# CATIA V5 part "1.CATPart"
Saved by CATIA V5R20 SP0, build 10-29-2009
Part number: 1
Material "Steel": density 7860 kg/m3, Young's modulus 2e+11 Pa, Poisson ratio 0.266, thermal expansion 1.17e-05 1/K
Bounding box of the stored display mesh (mm): x -152.5 to 152.5, y -205 to 205, z -23 to 0
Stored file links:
  E:\Ehsan\Amoozesh\CATIA\CATIA Course\Advanced\Videos\Session-15\1.CATPart
  D:\CATIA V5R20\B20\intel_a\startup\materials\Catalog.CATMaterial
  D:\CATIA V5R20\B20\intel_a\resources\graphic\figures\CATIA_EnvironmentMap_Satin_512x512.jpg
  D:\CATIA V5R20\B20\intel_a\resources\graphic\figures\CATIA_EnvironmentMap_Soft_512x512.jpg
  D:\CATIA V5R20\B20\intel_a\resources\graphic\figures\CATIA_EnvironmentMap_YellowSatin_512x512.jpg
  D:\CATIA V5R20\B20\intel_a\resources\graphic\figures\CATIA_EnvironmentMap_Black_512x512.jpg
  D:\CATIA V5R20\B20\intel_a\resources\graphic\figures\CATIA_EnvironmentMap_Grey_512x512.jpg
  D:\CATIA V5R20\B20\intel_a\resources\graphic\figures\CATIA_EnvironmentMap_DSRed_512x512.jpg
  D:\CATIA V5R20\B20\intel_a\resources\graphic\figures\CATIA_EnvironmentMap_DSBrown_512x512.jpg
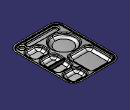
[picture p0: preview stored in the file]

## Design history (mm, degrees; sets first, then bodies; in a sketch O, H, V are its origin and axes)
SheetMetalParameters1: Thickness 0.5, BendRadius 4, KFactor 0.5 {= log(min(100,max(20*SheetMetalParameters1.BendRadius,SheetMetalParameters1.Thickness)/SheetMetalParameters1.Thickness))/log(100)/2}, ReliefRadialLength 1, ReliefAxialLength 2, MinimumBendRadius 0
Body1 (main body), material "Steel"
  Sketch1 on xy-plane, origin (0, 0, 0), H (0, -1, 0), V (1, 0, 0)
    line L1 (205, 102.5) -> (205, -102.5)
    line L2 (155, -152.5) -> (-155, -152.5)
    line L3 (-205, -102.5) -> (-205, 102.5)
    line L4 (-155, 152.5) -> (155, 152.5)
    arc A1 centre (155, 102.5) radius 50 from (205, 102.5) to (155, 152.5) ccw
    arc A2 centre (155, -102.5) radius 50 from (205, -102.5) to (155, -152.5) cw
    arc A3 centre (-155, -102.5) radius 50 from (-155, -152.5) to (-205, -102.5) cw
    arc A4 centre (-155, 102.5) radius 50 from (-205, 102.5) to (-155, 152.5) cw
    distance L2 L4 = 305
    distance L1 L3 = 410
    radius A1 = 50
    radius A2 = 50 {= Sketch1.radius(A1)}
    radius A3 = 50 {= Sketch1.radius(A1)}
    radius A4 = 50 {= Sketch1.radius(A1)}
    vertical: L1 V, L3 V
    horizontal: L2 H, L4 H
    equidistance: L1 L3 O, L2 L4 O
    tangency: A1 L1, A1 L4, A2 L1, A2 L2, A3 L2, A3 L3, A4 L3, A4 L4
  Wall1: Thickness 0.5, Profile Sketch1
  d_Stamp1: NewRoot_AttribNormalisation "No Standard", Stamp_FilletRadius 3, Stamp_IntersectFilletRadius 2
  d_Stamp2: NewRoot_AttribNormalisation "No Standard", Stamp_FilletRadius 5, Stamp_IntersectFilletRadius 2
  d_Stamp3: NewRoot_AttribNormalisation "No Standard", Stamp_FilletRadius 2, Stamp_IntersectFilletRadius 2
  d_Stamp4: NewRoot_AttribNormalisation "No Standard", Stamp_FilletRadius 5, Stamp_IntersectFilletRadius 2
  Sketch2 on face of d_Stamp1, origin (0, 0, -3), H (0, -1, 0), V (1, 0, 0)
    circle A1 centre (167, 104.5) radius 18
    point P1 (167, 104.5)
    construction line L1 (167, 60.5) -> (167, -104.5)
    point P3 (167, -104.5)
    line L2 (185, 60.5) -> (185, -104.5)
    line L3 (149, -104.5) -> (149, 60.5)
    arc A2 centre (167, -104.5) radius 18 from (185, -104.5) to (149, -104.5) cw
    arc A3 centre (167, 60.5) radius 18 from (149, 60.5) to (185, 60.5) cw
    reference projected line E1 (205, -102.5) -> (205, 102.5) from edge [face of Wall1 | face of Wall1]
    reference projected line E2 (-155, -152.5) -> (155, -152.5) from edge [face of Wall1 | face of Wall1]
    reference projected line E3 (155, 152.5) -> (-155, 152.5) from edge [face of Wall1 | face of Wall1]
    distance L1 L2 = 18
    distance L2 E1 = 20
    distance P3 E2 = 48
    radius A1 = 18
    distance P1 E3 = 48
    length L1 = 165
    vertical: L1 V
    tangency: A2 L2, A3 L2, A2 L3, A3 L3, L2 A1
  Sketch3 on face of d_Stamp2, origin (0, 0, -23), H (0, 1, 0), V (1, 0, 0)
    line L1 (22.5, 135.6754) -> (22.5, 24.3246)
    point P1 (22.5, 135.6754)
    point P2 (22.5, 24.3246)
    reference projected line E1 (67.1947, 102.5) -> (67.1947, 57.5) from edge [face of d_Stamp2 | face of d_Stamp2]
    reference projected line E2 (-22.1947, 57.5) -> (-22.1947, 102.5) from edge [face of d_Stamp2 | face of d_Stamp2]
    reference projected line E3 (-15, 24.3246) -> (60, 24.3246) from edge [face of d_Stamp1 | face of d_Stamp2]
    reference projected line E4 (60, 135.6754) -> (-15, 135.6754) from edge [face of d_Stamp1 | face of d_Stamp2]
    vertical: L1 V
    symmetry: E1 E2 L1
    coincidence: P2 E3, P1 E4
  Sketch4 on face of d_Stamp1, origin (0, 0, -3), H (0, -1, 0), V (1, 0, 0)
    point P1 (-102.5, -57.5)
    line L1 (-20, -12.5) -> (-20, -102.5)
    line L2 (-50, -132.5) -> (-155, -132.5)
    line L3 (-185, -102.5) -> (-185, -12.5)
    line L4 (-155, 17.5) -> (-50, 17.5)
    circle A1 centre (65, -57.5) radius 75
    point P3 (-142.5, 80)
    line L5 (-100, 102.5) -> (-100, 57.5)
    line L6 (-130, 27.5) -> (-155, 27.5)
    line L7 (-185, 57.5) -> (-185, 102.5)
    line L8 (-155, 132.5) -> (-130, 132.5)
    point P4 (-22.5, 80)
    line L9 (45, 102.5) -> (45, 57.5)
    line L10 (15, 27.5) -> (-60, 27.5)
    line L11 (-90, 57.5) -> (-90, 102.5)
    line L12 (-60, 132.5) -> (15, 132.5)
    point P5 (45, 27.5)
    reference projected line E1 (-205, 102.5) -> (-205, -102.5) from edge [face of Wall1 | face of Wall1]
    reference projected line E2 (155, 152.5) -> (-155, 152.5) from edge [face of Wall1 | face of Wall1]
    arc A2 centre (-50, -12.5) radius 30 from (-20, -12.5) to (-50, 17.5) ccw
    arc A3 centre (-50, -102.5) radius 30 from (-20, -102.5) to (-50, -132.5) cw
    arc A4 centre (-155, -102.5) radius 30 from (-155, -132.5) to (-185, -102.5) cw
    arc A5 centre (-155, -12.5) radius 30 from (-185, -12.5) to (-155, 17.5) cw
    arc A6 centre (-130, 102.5) radius 30 from (-100, 102.5) to (-130, 132.5) ccw
    point P18 (-100, 102.5)
    point P19 (-130, 132.5)
    arc A7 centre (-130, 57.5) radius 30 from (-100, 57.5) to (-130, 27.5) cw
    point P21 (-100, 57.5)
    point P22 (-130, 27.5)
    arc A8 centre (-155, 57.5) radius 30 from (-155, 27.5) to (-185, 57.5) cw
    point P24 (-155, 27.5)
    point P25 (-185, 57.5)
    arc A9 centre (-155, 102.5) radius 30 from (-185, 102.5) to (-155, 132.5) cw
    point P27 (-185, 102.5)
    point P28 (-155, 132.5)
    arc A10 centre (15, 102.5) radius 30 from (45, 102.5) to (15, 132.5) ccw
    arc A11 centre (15, 57.5) radius 30 from (45, 57.5) to (15, 27.5) cw
    arc A12 centre (-60, 57.5) radius 30 from (-60, 27.5) to (-90, 57.5) cw
    arc A13 centre (-60, 102.5) radius 30 from (-90, 102.5) to (-60, 132.5) cw
    reference projected line E3 (-155, -152.5) -> (155, -152.5) from edge [face of Wall1 | face of Wall1]
    axis line L13 (-22.5, 80) -> (-22.5, 154.5711)
    point P43 (110, 132.5)
    point P44 (140, 102.5)
    point P45 (140, 57.5)
    point P46 (110, 27.5)
    point P47 (85, 27.5)
    point P48 (55, 57.5)
    point P49 (85, 132.5)
    point P50 (55, 102.5)
    arc A14 centre (110, 102.5) radius 30 from (140, 102.5) to (110, 132.5) ccw
    arc A15 centre (110, 57.5) radius 30 from (110, 27.5) to (140, 57.5) ccw
    arc A16 centre (85, 57.5) radius 30 from (55, 57.5) to (85, 27.5) ccw
    arc A17 centre (85, 102.5) radius 30 from (55, 102.5) to (85, 132.5) cw
    line L14 (110, 132.5) -> (85, 132.5)
    line L15 (140, 57.5) -> (140, 102.5)
    line L16 (85, 27.5) -> (110, 27.5)
    line L17 (55, 102.5) -> (55, 57.5)
    distance L7 E1 = 20
    distance L8 E2 = 20
    distance L5 L11 = 10
    radius A2 = 30
    radius A3 = 30 {= Sketch4.radius(A2)}
    radius A4 = 30 {= Sketch4.radius(A2)}
    radius A5 = 30 {= Sketch4.radius(A2)}
    radius A6 = 30 {= Sketch4.radius(A2)}
    radius A7 = 30 {= Sketch4.radius(A2)}
    radius A8 = 30 {= Sketch4.radius(A2)}
    radius A9 = 30 {= Sketch4.radius(A2)}
    radius A10 = 30 {= Sketch4.radius(A2)}
    radius A11 = 30 {= Sketch4.radius(A2)}
    radius A12 = 30 {= Sketch4.radius(A2)}
    radius A13 = 30 {= Sketch4.radius(A2)}
    distance L2 E3 = 20
    distance L7 L5 = 85
    distance L11 L9 = 135
    distance L2 L4 = 150
    distance L6 L4 = 10
    distance A1 L1 = 10
    vertical: L1 V, L3 V, L5 V, L7 V, L9 V, L11 V, L13 V
    horizontal: L2 H, L4 H, L6 H, L8 H, L10 H, L12 H
    equidistance: L1 L3 P1, L2 L4 P1, L5 L7 P3, L6 L8 P3, L9 L11 P4, L10 L12 P4
    tangency: A1 L4, A1 L2, A2 L1, A2 L4, A3 L1, A3 L2, A4 L2, A4 L3, A5 L3, A5 L4, A6 L5, A6 L8, A7 L5, A7 L6, A8 L6, A8 L7, A9 L7, A9 L8, A10 L9, A10 L12, A11 L9, A11 L10, A12 L10, A12 L11, A13 L11, A13 L12, A1 L15
    coincidence: P5 L6, L12 L8, L3 L7, L9 P5, L10 P5
    symmetry: P28 P43 L13, P27 P44 L13, P25 P45 L13, P24 P46 L13, P22 P47 L13, P21 P48 L13, P19 P49 L13, P18 P50 L13, A9 A14 L13, A8 A15 L13, A7 A16 L13, A6 A17 L13, L8 L14 L13, L7 L15 L13, L6 L16 L13, L5 L17 L13
  Sketch5 on face of Wall1, origin (0, 0, 0), H (0, -1, 0), V (1, 0, 0)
